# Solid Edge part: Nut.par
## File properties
Author: Sarvanan
Template: sync iso part.par
Last saved by: CADCIM
Revision: 9
Application: Solid Edge
Accuracy: 0.990
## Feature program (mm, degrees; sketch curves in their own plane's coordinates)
sketch for "Hole_1" plane through (21.0838, 43.6973, 8) normal (0, 0, 1) x-axis (1, 0, 0)
  hole centre (-1.3414, 0.2221) bore radius 6
hole "Hole_1" diameter 12 through
pattern "unnamed Pattern 1" of "Hole_1"
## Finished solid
Body 1: solid body, 21 faces, 56 edges, 36 vertices.
  Faces by surface: spun 12, plane 8, cylinder 1
  Edges by curve: circle 18, line 18, intersection 17, spline 3
Bounding box of the edges (mm; curved faces can reach further): 30.022 x 26.000 x 12.000, from (4.7313, 30.9194, 0) to (34.7535, 56.9194, 12).
Cylindrical faces by radius (mm): R6 x1
Planar faces by outward normal: +y 1, +z 1, -y 1, -z 1, oblique 4
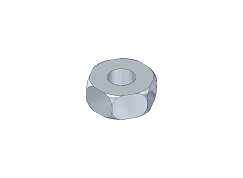
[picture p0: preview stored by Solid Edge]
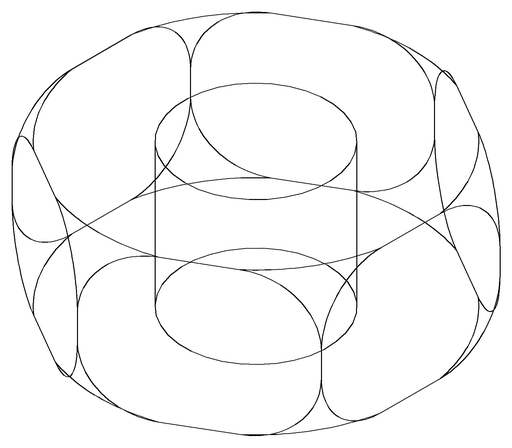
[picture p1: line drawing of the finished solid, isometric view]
